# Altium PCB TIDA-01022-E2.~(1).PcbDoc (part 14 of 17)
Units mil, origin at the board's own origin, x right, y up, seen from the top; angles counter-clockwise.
Board outline 6929.13 x 11614.17 mil, 12 copper layers (L1_Top Layer, L2_GND, L3_GND, L4_Signal Layer 1, L5_GND, L6_PWR, L7_GND/PWR, L8_PWR, L9_GND/PWR, L10_Signal Layer 2, L11_GND, L12_Bottom Layer), stack 64.6 mil thick; 1711 components, 1001 nets, 5985 pads, 3200 vias.
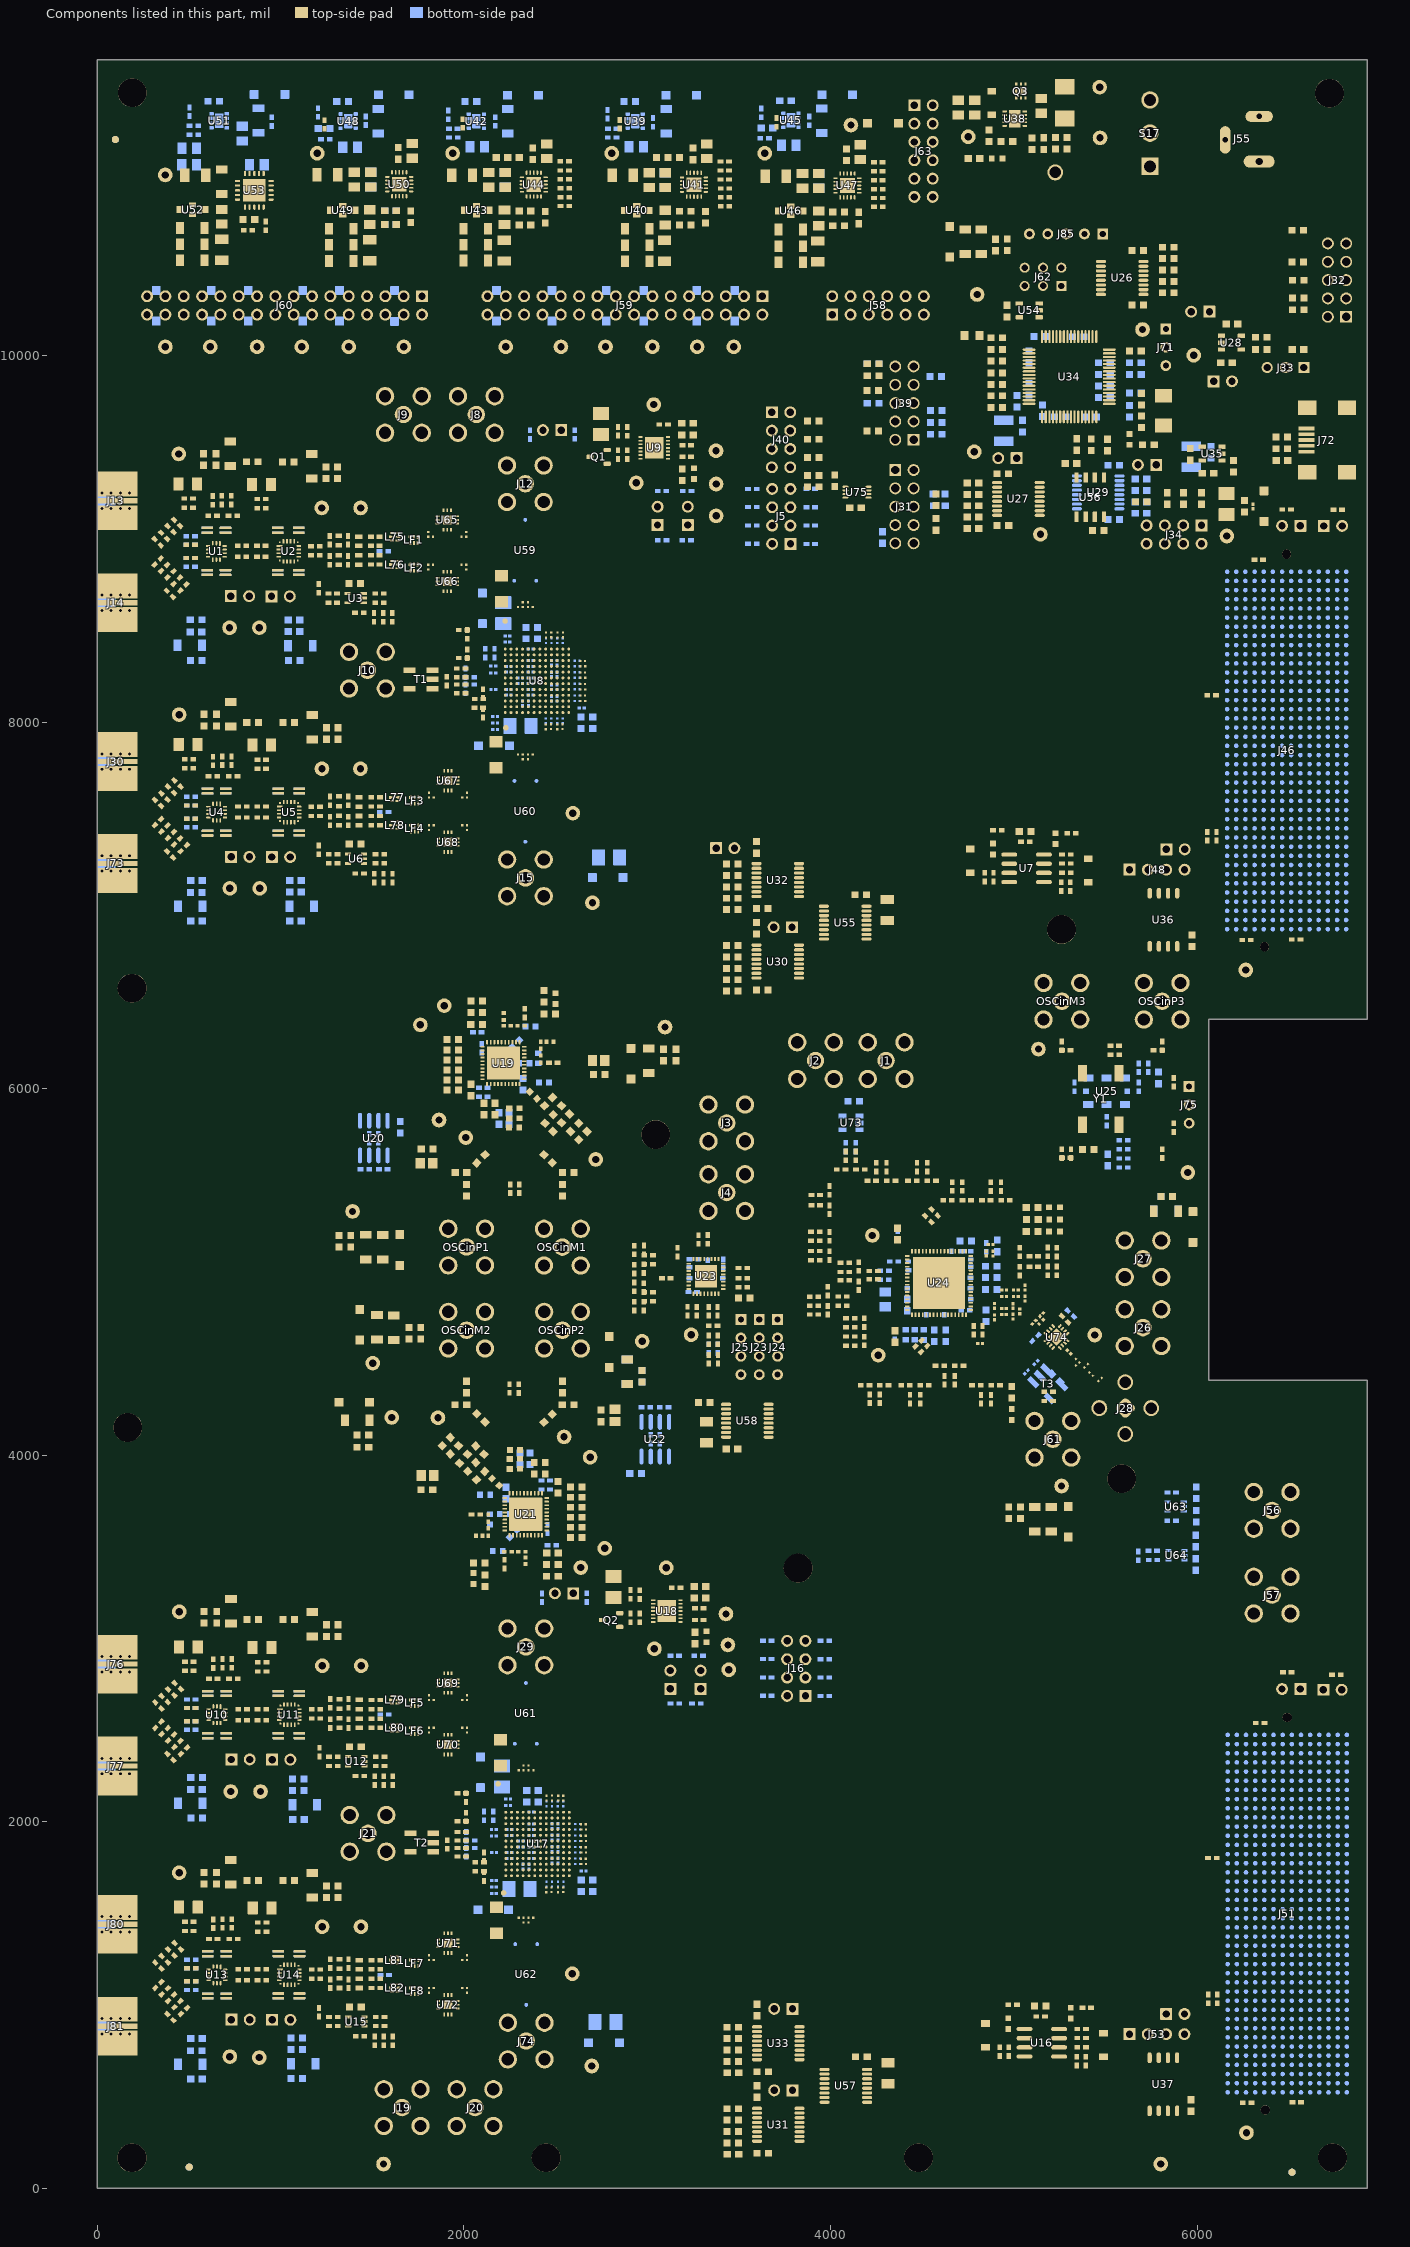
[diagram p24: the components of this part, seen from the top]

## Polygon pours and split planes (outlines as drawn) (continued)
GND on L12_Bottom Layer "V" (solid, pour order 876): 34 vertices, not listed, extent 1183.13,11091.37 1570.7,11445
VA_N1P25_LMH6401_4 on L12_Bottom Layer "V" (solid, pour order 352): 1080.17,572.83 1080.17,842.83 1070.17,852.83 985.17,852.83 975.17,842.83 975.17,577.83 985.17,567.83 1077.43,567.83 1080.17,570.57
AGND on L12_Bottom Layer "V" (solid, pour order 350): 1100.56,742.71 1100.56,843.23 1110.17,852.83 1165.17,852.83 1185.17,832.83 1185.17,757.83 1220.17,722.83 1220.17,653.9 1206.37,640.1 1153.17,640.1 1143.17,650.1 1143.17,699.83 1120.17,722.83
AGND on L12_Bottom Layer "V" (solid, pour order 348): 529.74,742.94 529.74,852.94 519.74,862.94 419.74,862.94 409.74,852.94 409.74,647.94 419.74,637.94 474.74,637.94 484.74,647.94 484.74,697.94
VA_N1P25_LMH5401_4 on L12_Bottom Layer "V" (solid, pour order 346): 564.39,560.94 630.94,560.94 637.23,567.24 637.23,838.1 624.39,850.94 562.23,850.94 552.23,840.94 552.23,725.94 552.23,573.1
VA_N1P25_LMH6401_3 on L12_Bottom Layer "V" (solid, pour order 334): 1089.5,1986.91 1089.5,2256.91 1079.5,2266.91 994.5,2266.91 984.5,2256.91 984.5,1991.91 994.5,1981.91 1086.76,1981.91 1089.5,1984.65
AGND on L12_Bottom Layer "V" (solid, pour order 332): 1109.9,2156.78 1109.9,2257.3 1119.5,2266.91 1174.5,2266.91 1194.5,2246.91 1194.5,2171.91 1229.5,2136.91 1229.5,2067.97 1215.7,2054.18 1162.5,2054.18 1152.5,2064.18 1152.5,2113.91 1129.5,2136.91
AGND on L12_Bottom Layer "V" (solid, pour order 330): 530.66,2167.28 530.66,2277.28 520.66,2287.28 420.66,2287.28 410.66,2277.28 410.66,2072.28 420.66,2062.28 475.66,2062.28 485.66,2072.28 485.66,2122.28
VA_N1P25_LMH5401_3 on L12_Bottom Layer "V" (solid, pour order 328): 565.32,1985.28 631.86,1985.28 638.16,1991.57 638.16,2262.44 625.32,2275.28 563.16,2275.28 553.16,2265.28 553.16,2150.28 553.16,1997.44
VA_N1P25_LMH6401_2 on L12_Bottom Layer "V" (solid, remove dead copper, pour order 316): 1073.8,6888.01 1073.8,7158.01 1063.8,7168.01 978.8,7168.01 968.8,7158.01 968.8,6893.01 978.8,6883.01 1071.06,6883.01 1073.8,6885.75
AGND on L12_Bottom Layer "V" (solid, pour order 314): 1094.2,7057.88 1094.2,7158.4 1103.8,7168.01 1158.8,7168.01 1178.8,7148.01 1178.8,7073.01 1213.8,7038.01 1213.8,6969.07 1200,6955.27 1146.8,6955.27 1136.8,6965.27 1136.8,7015.01 1113.8,7038.01
AGND on L12_Bottom Layer "V" (solid, pour order 312): 529.56,7061.57 529.56,7171.57 519.56,7181.57 419.56,7181.57 409.56,7171.57 409.56,6966.57 419.56,6956.57 474.56,6956.57 484.56,6966.57 484.56,7016.57
VA_N1P25_LMH5401_2 on L12_Bottom Layer "V" (solid, pour order 310): 564.22,6879.57 630.76,6879.57 637.06,6885.87 637.06,7156.74 624.22,7169.58 562.06,7169.57 552.06,7159.57 552.06,7044.57 552.06,6891.74
VA_N1P25_LMH5401_1 on L12_Bottom Layer "V" (solid, pour order 298): 562.42,8301.7 628.97,8301.7 635.26,8308 635.26,8578.86 622.42,8591.7 560.26,8591.7 550.26,8581.7 550.26,8466.7 550.26,8313.86
AGND on L12_Bottom Layer "V" (solid, pour order 296): 527.77,8483.7 527.77,8593.7 517.77,8603.7 417.77,8603.7 407.77,8593.7 407.77,8388.7 417.77,8378.7 472.77,8378.7 482.77,8388.7 482.77,8438.7
AGND on L12_Bottom Layer "V" (solid, pour order 294): 1086.32,8479.68 1086.32,8580.2 1095.93,8589.81 1150.93,8589.81 1170.93,8569.81 1170.93,8494.81 1205.93,8459.81 1205.93,8390.87 1192.13,8377.07 1138.93,8377.07 1128.93,8387.07 1128.93,8436.81 1105.93,8459.81
VA_N1P25_LMH6401_1 on L12_Bottom Layer "V" (solid, pour order 290): 1065.93,8309.81 1065.93,8579.81 1055.93,8589.81 970.93,8589.81 960.93,8579.81 960.93,8314.81 970.93,8304.81 1063.19,8304.81 1065.93,8307.55
VD1P1_ADC2 on L12_Bottom Layer "V" (solid, pour order 272): 2755.65,953.32 2755.65,620.32 2719.65,584.32 2605.65,584.32 2597.65,592.32 2591.65,598.32 2591.65,852.32 2591.65,949.32 2599.65,957.32 2752.65,957.32 2755.65,954.32
VD1P1_ADC1 on L12_Bottom Layer "V" (solid, pour order 270): 2776.87,7317.72 2776.87,6984.72 2740.87,6948.72 2626.87,6948.72 2618.87,6956.72 2612.87,6962.72 2612.87,7216.72 2612.87,7313.72 2620.87,7321.72 2773.87,7321.72 2776.87,7318.72
GND on L12_Bottom Layer "h" (solid, pour order 144): 3136.42,10944.6 2976.42,10944.6 2967.42,10935.6 2967.42,10836.73 2973.51,10830.64 3123.51,10830.64 3137.92,10845.05 3137.92,10940.1 3133.42,10944.6
V1P1V on L12_Bottom Layer "h" (solid, pour order 88): 2815,625 2809.68,630.32 2809.68,823.91 2818.34,832.57 2931.43,832.57 2943,821 2943,633 2935,625
V1P1V on L12_Bottom Layer "h" (solid, pour order 90): 2834,6982 2828.66,6987.34 2828.66,7175.71 2837.32,7184.37 2944.63,7184.37 2961,7168 2961,6992 2951,6982
GND on L12_Bottom Layer "V" (solid, pour order 516): 34 vertices, not listed, extent 3609,11095.33 3986.49,11452
GND on L12_Bottom Layer "V" (solid, pour order 866): 34 vertices, not listed, extent 2761.45,11104.83 3137.49,11452
GND on L12_Bottom Layer "V" (solid, pour order 868): 34 vertices, not listed, extent 1894.45,11107 2270.49,11452
VA1P1_ADC2 on L12_Bottom Layer "V" (solid, pour order 880): 17 vertices, not listed, extent 2058.26,2090 2370,2230
VA1P9_ADC2 on L12_Bottom Layer "V" (solid, pour order 882): 2260,1490 2175,1490 2170,1495 2165,1500 2165,1595 2165,1690 2170,1695 2191.69,1695 2201.69,1685 2206.69,1680 2240,1680 2280,1680 2285,1675 2285,1510 2265,1490
VA1P9_ADC1 on L12_Bottom Layer "V" (solid, pour order 884): 2256.67,7836 2171.67,7836 2166.67,7841 2161.67,7846 2161.67,7941 2161.67,8036 2166.67,8041 2188.36,8041 2198.36,8031 2203.36,8026 2236.67,8026 2276.67,8026 2281.67,8021 2281.67,7856 2261.67,7836
VA1P1_ADC1 on L12_Bottom Layer "V" (solid, pour order 886): 17 vertices, not listed, extent 2054.93,8436 2366.67,8576
NetC414_2 on L12_Bottom Layer "L1_Top Layer-No Net" (solid, pour order 946): 20 vertices, not listed, extent 5481,5542 5592,5770
DGND on L12_Bottom Layer "L1_Top Layer-No Net" (solid, pour order 948): 5606,5715 5606,5560 5615,5551 5667,5551 5673,5557 5673,5731 5666,5738 5618,5738 5606,5726
DGND on L12_Bottom Layer "L1_Top Layer-No Net" (solid, pour order 950): 5810,5448 5703,5448 5691,5436 5691,5298 5702,5287 5807,5287 5817,5297 5817,5441
V3P3_LMK61E2 on L12_Bottom Layer "L1_Top Layer-No Net" (solid, pour order 952): 5854,5285 5844,5295 5844,5452 5855,5463 6028,5463 6038,5453 6038,5300 6023,5285
DGND on L12_Bottom Layer "V" (solid, pour order 1160): 2119,10255 2344,10255 2360,10239 2360,9998 2352,9990 2107,9990 2095,10002 2095,10221 2095,10245 2105,10255
DGND on L12_Bottom Layer "V" (solid, pour order 1162): 2719,10255 2844,10255 2860,10239 2860,10001 2849,9990 2707,9990 2695,10002 2695,10221 2695,10245 2705,10255
DGND on L12_Bottom Layer "V" (solid, pour order 1164): 3219,10255 3344,10255 3360,10239 3360,10001 3349,9990 3207,9990 3195,10002 3195,10221 3195,10245 3205,10255
GND on L12_Bottom Layer "h" (solid, pour order 1274): 3973.4,10940.59 3813.4,10940.59 3804.4,10931.59 3804.4,10832.72 3810.49,10826.63 3960.49,10826.63 3974.9,10841.04 3974.9,10936.09 3970.4,10940.59
V1P1V_IN on L12_Bottom Layer "V" (solid, pour order 1348): 2405,10288 2392,10301 2392,10434 2410,10452 2655,10452 2664,10443 2664,10302 2650,10288
V1P9V_IN on L12_Bottom Layer "V" (solid, pour order 1352): 2901,10288 2891,10298 2891,10414 2929,10452 3152,10452 3162,10442 3162,10301 3149,10288
GND on L12_Bottom Layer "V" (solid, pour order 1356): 18 vertices, not listed, extent 2696,10291 2908.51,10730.64
V3P3_IN on L12_Bottom Layer "V" (solid, pour order 1362): 3393,10300 3393,10414 3398,10419 3878,10419 3893,10404 3893,10301 3881,10289 3404,10289 3393,10300
DGND on L12_Bottom Layer "12" (solid, remove dead copper, pour order 1749): 54 vertices, not listed, extent 1262,70 6899,10776
VA1P9_ADC2 on L6_PWR "12" (solid, pour order 1600): 2737.64,3036.11 2708.64,3007.11 2708.64,2693.36 2838.89,2563.11 3502.64,2563.11 4045.64,2563.11 4066.64,2584.11 4066.64,3018.72 4049.24,3036.11
VA1P9_ADC2 on L6_PWR "12" (solid, pour order 1598): 2249.33,1492 1868,1492 1848,1512 1848,2162.98 1911.03,2226 2303.33,2226 2334.09,2195.24 2334.09,2066.57 2334.09,1576.77
V1P1V on L6_PWR "12" (solid, pour order 1596): 2840.33,603 3007.05,602.73 3084,679.67 3084,2349 2898,2535 2059,2535 2041,2517 2041,2275 2069,2247 2638.33,2247 2803.33,2082 2803.33,620 2820.33,603
V1P1V on L6_PWR "12" (solid, pour order 1594): 2837,6949 3055.64,6948.64 3082,6975 3082,8532.19 2863.19,8751 2009,8751 1968,8710 1968,8606 1981,8593 2635,8593 2800,8428 2800,6966 2817,6949
VA1P9_ADC1 on L6_PWR "12" (solid, pour order 1590): 2656,9321 2627,9292 2627,8938 2675,8890 2717,8848 3421,8848 3964,8848 3985,8869 3985,9303.61 3967.61,9321
V3P3_LMX2RF on L6_PWR "12" (solid, pour order 1584): 1277.39,4363.39 1277.39,3765.61 1764,3279 2425,3279 2437,3291 2437,3526 2413,3550 2329,3550 2219,3660 1792,3660 1667,3785 1667,4337 1633,4371 1285,4371
V3P3_LMX2 on L6_PWR "12" (solid, pour order 1582): 21 vertices, not listed, extent 1277.39,3310 3042,4642.68
V3P3_LMX1RF on L6_PWR "12" (solid, pour order 1576): 2339,6260 2299,6220 1717,6220 1698,6239 1698,6391 1812,6505 1852,6545 2330,6545 3092,6545 3178,6545 3198.57,6524.43 3198.57,6400.77 3198.57,6296.57 3162,6260
V3P3 on L6_PWR "12" (solid, pour order 1560): 17 vertices, not listed, extent 1277.39,4478 2837,5340
V3P3_LMX1 on L6_PWR "12" (solid, pour order 1558): 1277.39,5185.61 1277.39,5962.43 1512.96,6198 2291.29,6198 2350.47,6257.18 2418.92,6257.18 2816.82,6257.18 2839.61,6234.39 2839.61,5481.61 2727,5369 1899,5369 1705.3,5175.3 1287.7,5175.3
V3P3_VDD on L6_PWR "12" (solid, pour order 1546): 37 vertices, not listed, extent 2627,6376.24 6867,10834
V3P3_VDD on L6_PWR "12" (solid, pour order 1544): 30 vertices, not listed, extent 2684,106 6082.44,4333
VA_N1P25 on L6_PWR "12" (solid, pour order 1530): 52 vertices, not listed, extent 53,496 1003,10255
VD1P1_ADC2 on L6_PWR "V" (solid, pour order 1202): 2630.2,602.73 2578.61,602.73 2545.33,636 2545.33,1422.67 2405.33,1562.67 2405.33,2059 2416.57,2070.24 2759.09,2070.24 2780.2,2049.14 2780.2,638.73 2744.2,602.73
VD1P1_ADC1 on L6_PWR "V" (solid, pour order 1196): 2626.87,6948.72 2575.28,6948.72 2542,6982 2542,7777 2402,7917 2402,8405 2413.24,8416.24 2755.76,8416.24 2776.87,8395.13 2776.87,6984.72 2740.87,6948.72
V3P3_LMK48XX on L6_PWR "V" (solid, pour order 1174): 21 vertices, not listed, extent 3254,3743 5877,6344
V3P3_LMK61E2 on L6_PWR "V" (solid, pour order 1172): 5702,5287 5526,5287 5400,5413 5074,5739 5074,6239 5074,6625 5126,6677 5919,6677 6003,6593 6003,5318 5972,5287 5703,5287
V3P3_LMK00304 on L6_PWR "V" (solid, pour order 1168): 3741,4362 2912,4362 2882,4392 2860,4414 2860,4960 2860,5206 2898,5244 3372,5244 3678,5244 3753,5169 3760.74,5161.26 3760.74,4758 3760.74,4381.74
VREGIN on L6_PWR "V" (solid, pour order 1166): 18 vertices, not listed, extent 5043.3,9556.44 5863.31,10075
VA_N1P25_LMH6401_1 on L6_PWR "V" (solid, pour order 1630): 18 vertices, not listed, extent 773,8296 1358,9333
VA_N1P25_LMH5401_1 on L6_PWR "V" (solid, pour order 1632): 24 vertices, not listed, extent 371.19,8301 865.67,9393
VA_N1P25_LMH5401_2 on L6_PWR "V" (solid, pour order 1646): 24 vertices, not listed, extent 372.99,6878.87 867.47,7970.87
VA_N1P25_LMH5401_3 on L6_PWR "V" (solid, pour order 1650): 24 vertices, not listed, extent 374.51,1954.64 868.99,3046.64
VA_N1P25_LMH5401_4 on L6_PWR "V" (solid, pour order 1654): 24 vertices, not listed, extent 374.59,535.3 869.07,1627.3
VA_N1P25_LMH6401_2 on L6_PWR "V" (solid, pour order 1699): 18 vertices, not listed, extent 774.8,6873.87 1359.8,7910.87
VA_N1P25_LMH6401_3 on L6_PWR "V" (solid, pour order 1701): 18 vertices, not listed, extent 776.32,1949.64 1361.32,2986.64
VA_N1P25_LMH6401_4 on L6_PWR "V" (solid, pour order 1703): 18 vertices, not listed, extent 776.39,530.3 1361.39,1567.3
12VIN on L6_PWR "12" (solid, pour order 1705): 24 vertices, not listed, extent 2360,11210 4270,11452
12VIN on L6_PWR "12" (solid, pour order 1707): 17 vertices, not listed, extent 977,11210 4270,11559
VA1P9_ADC1 on L6_PWR "12" (solid, pour order 1709): 2246,7838 1864.67,7838 1844.67,7858 1844.67,8508.97 1907.69,8572 2300,8572 2330.76,8541.24 2330.76,8412.57 2330.76,7922.76
V3P3 on L6_PWR "12" (solid, pour order 1735): 4709,10776 4612,10776 4600,10764 4600,10216 4534,10150 3405,10150 3392,10137 3392,10000 3402,9990 4594,9990 4664,10060 4720,10116 4720,10765
V3P3_VDD on L8_PWR "12" (solid, pour order 1568): 19 vertices, not listed, extent 2886,106 6083,7428
VDDL19 on L8_PWR "12" (solid, pour order 1566): 4648,10658 4648,7526 4704,7470 4723,7451 5722,7451 6051,7451 6082,7482 6082,8935 6106,8959 6821,8959 6867,9005 6867,10804 6837,10834 4824,10834 4653,10663
V3P3 on L8_PWR "12" (solid, pour order 1562): 22 vertices, not listed, extent 2374,3460 5598,10255
VA3P75 on L8_PWR "12" (solid, pour order 1532): 51 vertices, not listed, extent 683,1613 1804,10255
VA1P1_ADC2 on L8_PWR "V" (solid, pour order 1222): 2145.34,2235 2130.33,2220 2130.33,1743 2155.33,1718 2599,1718 2615.33,1734.33 2615.33,2209 2615.33,2220 2600.33,2235
VA1P1_ADC1 on L8_PWR "V" (solid, pour order 1220): 2142.01,8581 2127,8566 2127,8089 2149,8067 2574,8067 2612,8105 2612,8555 2612,8566 2597,8581
VA1P9_ADC1 on L8_PWR "12" (solid, pour order 1624): 2640,9187 2640,8061 2617,8038 2177,8038 2175,8036 2175,7864 2183,7856 2831,7856 2884,7909 2884,9185 2846,9223 2658,9223 2640,9205
VA1P9_ADC2 on L8_PWR "12" (solid, pour order 1626): 2628.18,2698.18 2628.18,1722.18 2594,1688 2172,1688 2167,1683 2167,1511 2180.09,1497.91 2819.18,1497.91 2864,1542.73 2864,2702 2848,2718 2648,2718
VA3P75_LMH5401_1 on L8_PWR "V" (solid, pour order 1638): 371.19,9549.2 391,9569 833,9569 865.67,9536.33 865.67,8634.66 834.02,8603 412,8603 371.19,8643.81
VA3P75_LMH6401_1 on L8_PWR "V" (solid, pour order 1640): 1326,9333 915,9333 895.67,9313.67 895.67,8644.66 935.68,8604.66 1345.66,8604.66 1358,8617 1358,9301
VA3P75_LMH6401_2 on L8_PWR "V" (solid, pour order 1658): 1327.8,7910.87 916.8,7910.87 897.47,7891.55 897.47,7222.53 937.47,7182.53 1347.45,7182.53 1359.8,7194.87 1359.8,7878.87
VA3P75_LMH5401_2 on L8_PWR "V" (solid, pour order 1660): 372.99,8127.07 392.8,8146.87 834.8,8146.87 867.47,8114.2 867.47,7212.53 835.82,7180.87 413.8,7180.87 372.99,7221.68
VA3P75_LMH6401_3 on L8_PWR "V" (solid, pour order 1662): 1329.31,2986.64 918.32,2986.64 898.99,2967.31 898.99,2298.29 938.99,2258.29 1348.97,2258.29 1361.32,2270.64 1361.32,2954.64
VA3P75_LMH5401_3 on L8_PWR "V" (solid, pour order 1664): 374.51,3202.83 394.32,3222.64 836.32,3222.64 868.99,3189.96 868.99,2288.29 837.34,2256.64 415.32,2256.64 374.51,2297.44
VA3P75_LMH6401_4 on L8_PWR "V" (solid, pour order 1666): 1329.39,1567.3 918.39,1567.3 899.07,1547.98 899.07,878.96 939.07,838.96 1349.05,838.96 1361.39,851.3 1361.39,1535.3
VA3P75_LMH5401_4 on L8_PWR "V" (solid, pour order 1668): 374.59,1783.5 394.39,1803.3 836.39,1803.3 869.07,1770.63 869.07,868.96 837.41,837.3 415.39,837.3 374.59,878.11
DGND on L2_GND "12" (solid, remove dead copper, pour order 1674): 112 vertices, not listed, extent 1262,70 6899,10776
AGND on L2_GND "12" (solid, remove dead copper, pour order 1672): 95 vertices, not listed, extent 17.27,478 2555.33,10255
GND on L2_GND "12" (solid, pour order 1398): 21 vertices, not listed, extent 1860,10291 4609,11452
GND on L2_GND "12" (solid, pour order 1396): 27 vertices, not listed, extent 91,10273 6865,11579.37
DGND on L11_GND "12" (solid, remove dead copper, pour order 1478): 54 vertices, not listed, extent 1262,70 6899,10776
GND on L11_GND "12" (solid, pour order 1518): 27 vertices, not listed, extent 91,10273 6865,11579.37
GND on L11_GND "12" (solid, pour order 1516): 21 vertices, not listed, extent 1860,10291 4609,11452
AGND on L11_GND "12" (solid, remove dead copper, pour order 1476): 26 vertices, not listed, extent 2152,2042.38 2554.99,3108.38
AGND on L11_GND "12" (solid, remove dead copper, pour order 1474): 25 vertices, not listed, extent 2121.91,650.23 2522,1716.23
AGND on L11_GND "12" (solid, remove dead copper, pour order 1472): 26 vertices, not listed, extent 2140,6996.2 2517,8062.2
AGND on L11_GND "12" (solid, remove dead copper, pour order 1470): 26 vertices, not listed, extent 2160,8388 2552,9454
AGND on L11_GND "12" (solid, remove dead copper, pour order 1695): 45 vertices, not listed, extent 17.27,478 1804,10255
DGND on L5_GND "12" (solid, remove dead copper, pour order 1688): 101 vertices, not listed, extent 873,70 6899,10776
GND on L5_GND "12" (solid, pour order 1506): 27 vertices, not listed, extent 91,10273 6865,11579.37
GND on L5_GND "12" (solid, pour order 1504): 21 vertices, not listed, extent 1860,10291 4609,11452
AGND on L5_GND "12" (solid, remove dead copper, pour order 1691): 83 vertices, not listed, extent 17.27,478 2521.36,10255
DGND on L3_GND "12" (solid, remove dead copper, pour order 1684): 112 vertices, not listed, extent 1262,70 6899,10776
AGND on L3_GND "12" (solid, remove dead copper, pour order 1680): 95 vertices, not listed, extent 17.27,478 2555.33,10255
GND on L3_GND "12" (solid, pour order 1502): 27 vertices, not listed, extent 91,10273 6865,11579.37
GND on L3_GND "12" (solid, pour order 1500): 21 vertices, not listed, extent 1860,10291 4609,11452
GND on L7_GND/PWR "12" (solid, pour order 1510): 27 vertices, not listed, extent 91,10273 6865,11579.37
GND on L7_GND/PWR "12" (solid, pour order 1508): 21 vertices, not listed, extent 1860,10291 4609,11452
AGND on L7_GND/PWR "12" (solid, remove dead copper, pour order 1711): 95 vertices, not listed, extent 17.27,478 2555.33,10255
V1P9V on L7_GND/PWR "12" (solid, remove dead copper, pour order 1713): 111 vertices, not listed, extent 1262,103 6867,10776
GND on L9_GND/PWR "12" (solid, pour order 1514): 27 vertices, not listed, extent 91,10273 6865,11579.37
GND on L9_GND/PWR "12" (solid, pour order 1512): 21 vertices, not listed, extent 1860,10291 4609,11452
AGND on L9_GND/PWR "12" (solid, remove dead copper, pour order 1715): 95 vertices, not listed, extent 17.27,478 2555.33,10255
V1P1V on L9_GND/PWR "12" (solid, remove dead copper, pour order 1717): 111 vertices, not listed, extent 1262,103 6867,10776
V1P9V on L4_Signal Layer 1 "L1_Top Layer-No Net" (solid, pour order 1574): 20 vertices, not listed, extent 2787,8961 6883,10834

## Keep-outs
Keep-Out Layer:
  text ".Layer_Name" at -2293.76,-2323.68 h60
